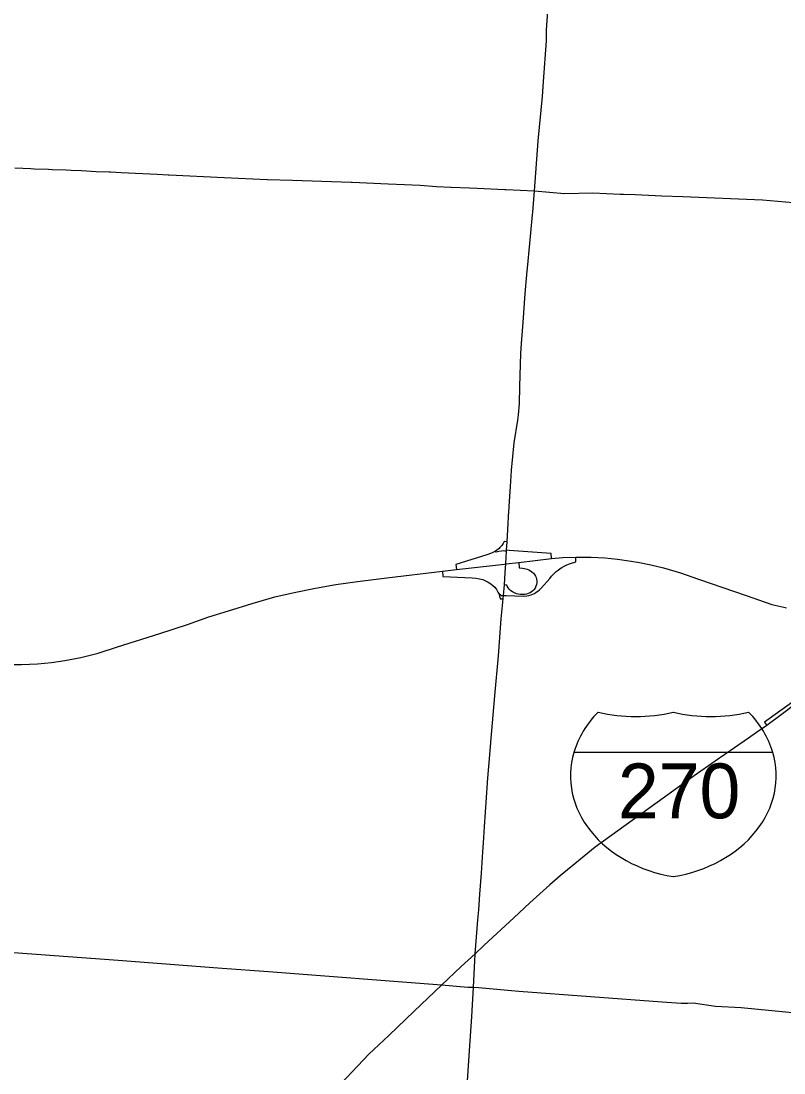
# Model space of a CAD drawing. Extents: x -1146 to -445, y -1283 to -822.
# Drawn here: x -821.35 to -786.59, y -1104.58 to -1056.63 of the extents above; entities that cross this region are included whole.
import ezdxf

# ---------------------------------------------------------------- set-up
doc = ezdxf.new("R2010")
doc.units = 0
for name, color, linetype in [('GM_X_Interchange_Ramps', 7, 'Continuous'), ('GM_X_Interstate_Route', 7, 'Continuous'), ('GM_X_Interstate_Shield', 7, 'Continuous'), ('GM_X_State_Route', 7, 'Continuous'), ('GM_X_Township', 7, 'Continuous'), ('GM_X_US_Route', 7, 'Continuous')]:
    doc.layers.add(name, color=color, linetype=linetype)

msp = doc.modelspace()

# ---------------------------------------------------------------- linework, layer by layer
at = {"layer": 'GM_X_Interchange_Ramps'}
for points in [[(-799.201, -1080.365), (-799.331, -1080.355), (-799.384, -1080.442), (-799.419, -1080.493), (-799.448, -1080.532), (-799.486, -1080.578), (-799.529, -1080.624), (-799.568, -1080.663), (-799.622, -1080.711), (-799.664, -1080.745), (-799.733, -1080.796), (-799.917, -1080.883), (-800.124, -1080.96), (-801.541, -1081.397), (-801.512, -1081.628)], [(-799.226, -1080.793), (-799.31, -1080.785), (-799.363, -1080.784), (-799.457, -1080.79), (-799.574, -1080.813), (-799.706, -1080.837), (-799.733, -1080.796)], [(-797.175, -1081.124), (-797.196, -1080.905), (-799.113, -1080.757), (-799.224, -1080.747)], [(-799.372, -1082.808), (-799.245, -1082.816), (-798.448, -1082.846), (-798.301, -1082.831), (-798.211, -1082.812), (-798.106, -1082.78), (-798.034, -1082.751), (-797.959, -1082.716), (-797.872, -1082.666), (-797.796, -1082.613), (-797.721, -1082.551), (-797.633, -1082.464), (-797.262, -1082.041), (-797.178, -1081.937), (-797.118, -1081.872), (-797.032, -1081.786), (-796.961, -1081.723), (-796.879, -1081.657), (-796.785, -1081.589), (-796.703, -1081.536), (-796.607, -1081.481), (-796.513, -1081.434), (-796.409, -1081.388), (-796.319, -1081.354), (-796.078, -1081.279), (-796.073, -1081.06)], [(-802.152, -1081.706), (-802.134, -1081.947), (-800.8, -1082.014), (-800.622, -1082.029), (-800.461, -1082.052), (-800.316, -1082.09), (-800.189, -1082.141), (-800.066, -1082.2), (-799.946, -1082.279), (-799.855, -1082.358), (-799.768, -1082.439), (-799.689, -1082.544), (-799.62, -1082.654), (-799.569, -1082.748), (-799.56, -1082.78), (-799.544, -1082.842), (-799.535, -1082.89), (-799.513, -1082.963), (-799.386, -1082.972)], [(-798.675, -1081.307), (-798.652, -1081.545), (-798.504, -1081.563), (-798.422, -1081.577), (-798.343, -1081.595), (-798.283, -1081.612), (-798.207, -1081.641), (-798.13, -1081.684), (-798.071, -1081.727), (-798, -1081.795), (-797.95, -1081.857), (-797.907, -1081.926), (-797.876, -1081.992), (-797.858, -1082.068), (-797.85, -1082.148), (-797.853, -1082.236), (-797.865, -1082.309), (-797.889, -1082.388), (-797.93, -1082.475), (-797.983, -1082.553), (-798.026, -1082.601), (-798.088, -1082.653), (-798.147, -1082.685), (-798.239, -1082.723), (-798.319, -1082.747), (-798.399, -1082.763), (-798.498, -1082.771), (-798.591, -1082.768), (-798.685, -1082.755), (-798.779, -1082.731), (-798.868, -1082.696), (-798.951, -1082.653), (-799.036, -1082.596), (-799.105, -1082.525), (-799.152, -1082.46), (-799.194, -1082.387), (-799.216, -1082.336), (-799.328, -1082.329)], [(-799.569, -1082.748), (-799.548, -1082.741), (-799.504, -1082.785), (-799.455, -1082.808), (-799.372, -1082.808)], [(-785.164, -1086.934), (-787.48, -1088.581), (-787.369, -1088.733)]]:
    msp.add_lwpolyline(points, dxfattribs=at)
at = {"layer": 'GM_X_Interstate_Route'}
for points in [[(-799.319, -1081.382), (-799.261, -1081.376), (-798.675, -1081.307), (-797.175, -1081.124), (-796.666, -1081.08), (-796.073, -1081.06), (-795.372, -1081.063), (-794.743, -1081.098), (-794.179, -1081.164), (-793.553, -1081.245), (-793.167, -1081.306), (-792.65, -1081.411), (-792.083, -1081.547), (-791.298, -1081.781), (-790.473, -1082.074), (-788.306, -1082.814), (-787.138, -1083.227), (-786.587, -1083.349), (-786.463, -1083.375)], [(-822.051, -1085.953), (-821.335, -1085.959), (-820.606, -1085.921), (-819.968, -1085.868), (-819.355, -1085.779), (-818.62, -1085.635), (-817.832, -1085.441), (-816.961, -1085.159), (-815.03, -1084.552), (-813.773, -1084.141), (-812.789, -1083.79), (-811.899, -1083.517), (-810.823, -1083.171), (-809.781, -1082.875), (-808.903, -1082.676), (-807.936, -1082.476), (-807.01, -1082.317), (-806.014, -1082.172), (-804.682, -1082.01), (-802.152, -1081.706), (-801.512, -1081.628), (-799.319, -1081.382)], [(-784.901, -1086.891), (-786.657, -1088.203), (-787.369, -1088.733)], [(-787.369, -1088.733), (-787.839, -1089.061)], [(-788.403, -1089.454), (-789.718, -1090.372), (-790.671, -1091.038), (-795.185, -1094.284), (-796.789, -1095.588), (-797.261, -1096.008), (-798.174, -1096.828), (-798.897, -1097.513), (-800.253, -1098.753), (-800.655, -1099.148)], [(-787.839, -1089.061), (-788.206, -1089.317), (-788.403, -1089.454)], [(-800.655, -1099.148), (-801.293, -1099.728), (-802.193, -1100.582)], [(-802.193, -1100.582), (-803.442, -1101.758), (-804.597, -1102.868), (-805.506, -1103.728), (-806.515, -1104.793), (-807.247, -1105.509), (-807.849, -1106.161), (-808.05, -1106.398)]]:
    msp.add_lwpolyline(points, dxfattribs=at)
at = {"layer": 'GM_X_Interstate_Shield'}
msp.add_line((-787.095, -1089.963), (-796.16, -1089.963), dxfattribs=at)
msp.add_line((-787.095, -1089.963), (-796.16, -1089.963), dxfattribs=at)
for centre, start_param, end_param in [((-790.456, -1091.034), 2.47259, 2.911027), ((-793.34, -1083.644), 4.415841, 5.008937), ((-789.915, -1083.644), 4.415841, 5.008937), ((-792.799, -1091.034), 0.230566, 0.669003), ((-790.456, -1091.034), 2.911027, 4.511031), ((-792.799, -1091.034), 4.913747, 6.513751)]:
    msp.add_ellipse(centre, major_axis=(5.859, 0), ratio=0.8, start_param=start_param, end_param=end_param, dxfattribs=at)
at = {"layer": 'GM_X_State_Route'}
for points in [[(-797.403, -1057.025), (-797.34, -1056.197), (-797.339, -1056.179), (-797.303, -1055.633), (-797.3, -1055.583)], [(-797.542, -1059.386), (-797.409, -1057.536), (-797.406, -1057.066), (-797.403, -1057.025)], [(-797.951, -1064.364), (-797.79, -1062.108), (-797.788, -1062.087), (-797.591, -1060.071), (-797.542, -1059.386)], [(-798.298, -1068.162), (-798.273, -1067.887), (-798.174, -1066.762), (-798.039, -1065.458), (-798.029, -1065.334), (-797.951, -1064.364)], [(-798.618, -1073.279), (-798.576, -1071.774), (-798.544, -1071.321), (-798.474, -1070.374), (-798.376, -1069.044), (-798.3, -1068.189), (-798.299, -1068.173), (-798.298, -1068.162)], [(-798.689, -1074.581), (-798.641, -1074.067), (-798.618, -1073.279)], [(-799.119, -1078.947), (-799.113, -1078.851), (-799.107, -1078.753), (-799.05, -1077.846), (-799.003, -1077.119), (-799.003, -1077.105), (-798.883, -1075.856), (-798.712, -1074.818), (-798.689, -1074.581)], [(-799.243, -1081.072), (-799.226, -1080.793), (-799.224, -1080.747), (-799.201, -1080.365), (-799.169, -1079.811), (-799.119, -1078.947)], [(-799.289, -1081.77), (-799.261, -1081.376), (-799.243, -1081.072)], [(-799.766, -1087.389), (-799.59, -1085.564), (-799.469, -1083.883), (-799.468, -1083.881), (-799.386, -1082.972), (-799.372, -1082.808), (-799.328, -1082.329), (-799.289, -1081.77)], [(-800.262, -1093.849), (-800.23, -1093.36), (-800.094, -1091.348), (-800.093, -1091.328), (-799.948, -1089.522), (-799.947, -1089.505), (-799.766, -1087.389)], [(-800.307, -1094.496), (-800.278, -1094.087), (-800.263, -1093.853), (-800.262, -1093.849)], [(-800.444, -1096.435), (-800.443, -1096.433), (-800.376, -1095.471), (-800.307, -1094.5), (-800.307, -1094.496)], [(-800.53, -1097.598), (-800.53, -1097.595), (-800.493, -1097.142), (-800.444, -1096.435)], [(-800.624, -1098.76), (-800.624, -1098.76), (-800.53, -1097.598)], [(-800.728, -1100.686), (-800.655, -1099.148), (-800.624, -1098.76)], [(-800.813, -1101.999), (-800.728, -1100.686)], [(-800.916, -1103.575), (-800.813, -1101.999)], [(-801.078, -1106.07), (-800.916, -1103.575)]]:
    msp.add_lwpolyline(points, dxfattribs=at)
at = {"layer": 'GM_X_Township'}
msp.add_lwpolyline([(-784.642, -1101.989), (-788.532, -1101.616), (-789.708, -1101.547), (-790.726, -1101.398), (-790.973, -1101.408), (-791.271, -1101.412), (-792.141, -1101.357), (-798.668, -1100.86), (-800.511, -1100.693), (-800.728, -1100.686), (-800.993, -1100.68), (-802.193, -1100.582), (-810.083, -1099.974), (-812.193, -1099.818), (-816.926, -1099.458), (-825.428, -1098.824)], dxfattribs=at)
at = {"layer": 'GM_X_US_Route'}
for points in [[(-821.636, -1063.32), (-820.911, -1063.349), (-820.757, -1063.356), (-820.097, -1063.383), (-819.937, -1063.389), (-819.292, -1063.416), (-819.062, -1063.425), (-818.598, -1063.444), (-817.924, -1063.485), (-817.342, -1063.499), (-817.276, -1063.502)], [(-817.276, -1063.502), (-816.789, -1063.524), (-815.145, -1063.599), (-814.655, -1063.63), (-814.601, -1063.633), (-812.097, -1063.753), (-810.131, -1063.844), (-810.115, -1063.845), (-808.975, -1063.883), (-806.315, -1063.972), (-806.27, -1063.974), (-804.621, -1064.053), (-803.879, -1064.081), (-803.168, -1064.112), (-802.427, -1064.164), (-801.77, -1064.197), (-801.745, -1064.198), (-800.91, -1064.236), (-800.57, -1064.252), (-799.302, -1064.31), (-799.263, -1064.311), (-797.951, -1064.364)], [(-797.951, -1064.364), (-796.589, -1064.487), (-795.302, -1064.454), (-794.049, -1064.512), (-793.903, -1064.518)], [(-793.903, -1064.518), (-793.363, -1064.54)], [(-793.363, -1064.54), (-792.147, -1064.59)], [(-792.147, -1064.59), (-791.202, -1064.629), (-787.566, -1064.782), (-785.822, -1064.934), (-784.628, -1064.953), (-782.338, -1064.99), (-780.946, -1065.094)]]:
    msp.add_lwpolyline(points, dxfattribs=at)

# ---------------------------------------------------------------- texts
at = {"layer": 'GM_X_Interstate_Shield'}
msp.add_text('270', height=2.5, dxfattribs=at).set_placement((-794.152, -1092.971))

doc.saveas('drawing.dxf')
